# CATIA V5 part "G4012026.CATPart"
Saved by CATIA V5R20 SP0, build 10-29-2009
Part number: G4012026
Revision: 4
Definition: design
Nomenclature: G4012026
Source: made
Description: NOT SPECIFIED
Bounding box of the stored display mesh (mm): x 0 to 26, y -16 to 16, z -16 to 16
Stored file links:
  C:\Users\Raffaele\Desktop\3D X SITO CF\BOLEX\25-BUSH REF 401\G4012026.CATPart
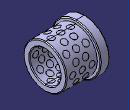
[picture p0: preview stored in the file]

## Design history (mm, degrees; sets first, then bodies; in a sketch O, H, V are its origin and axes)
Body1 "MANIFOLD_SOLID_BREP #5937" (main body)
  Solid1: solid without history
Body2 "MANIFOLD_SOLID_BREP #6084"
  Solid2: solid without history
Body3 "MANIFOLD_SOLID_BREP #6231"
  Solid3: solid without history
Body4 "MANIFOLD_SOLID_BREP #6378"
  Solid4: solid without history
Body5 "MANIFOLD_SOLID_BREP #6525"
  Solid5: solid without history
Body6 "MANIFOLD_SOLID_BREP #6674"
  Solid6: solid without history
Body7 "MANIFOLD_SOLID_BREP #6823"
  Solid7: solid without history
Body8 "MANIFOLD_SOLID_BREP #6972"
  Solid8: solid without history
Body9 "MANIFOLD_SOLID_BREP #7121"
  Solid9: solid without history
Body10 "MANIFOLD_SOLID_BREP #7270"
  Solid10: solid without history
Body11 "MANIFOLD_SOLID_BREP #7419"
  Solid11: solid without history
Body12 "MANIFOLD_SOLID_BREP #7568"
  Solid12: solid without history
Body13 "MANIFOLD_SOLID_BREP #7717"
  Solid13: solid without history
Body14 "MANIFOLD_SOLID_BREP #7866"
  Solid14: solid without history
Body15 "MANIFOLD_SOLID_BREP #8015"
  Solid15: solid without history
Body16 "MANIFOLD_SOLID_BREP #8164"
  Solid16: solid without history
Body17 "MANIFOLD_SOLID_BREP #8313"
  Solid17: solid without history
Body18 "MANIFOLD_SOLID_BREP #8462"
  Solid18: solid without history
Body19 "MANIFOLD_SOLID_BREP #8611"
  Solid19: solid without history
Body20 "MANIFOLD_SOLID_BREP #8760"
  Solid20: solid without history
Body21 "MANIFOLD_SOLID_BREP #8909"
  Solid21: solid without history
Body22 "MANIFOLD_SOLID_BREP #9058"
  Solid22: solid without history
Body23 "MANIFOLD_SOLID_BREP #9207"
  Solid23: solid without history
Body24 "MANIFOLD_SOLID_BREP #9356"
  Solid24: solid without history
Body25 "MANIFOLD_SOLID_BREP #9505"
  Solid25: solid without history
Body26 "MANIFOLD_SOLID_BREP #9654"
  Solid26: solid without history
Body27 "MANIFOLD_SOLID_BREP #9803"
  Solid27: solid without history
Body28 "MANIFOLD_SOLID_BREP #9952"
  Solid28: solid without history
Body29 "MANIFOLD_SOLID_BREP #10101"
  Solid29: solid without history
Body30 "MANIFOLD_SOLID_BREP #10250"
  Solid30: solid without history
Body31 "MANIFOLD_SOLID_BREP #10399"
  Solid31: solid without history
Body32 "MANIFOLD_SOLID_BREP #10548"
  Solid32: solid without history
Body33 "MANIFOLD_SOLID_BREP #10695"
  Solid33: solid without history
Body34 "MANIFOLD_SOLID_BREP #10842"
  Solid34: solid without history
Body35 "MANIFOLD_SOLID_BREP #10991"
  Solid35: solid without history
Body36 "MANIFOLD_SOLID_BREP #11140"
  Solid36: solid without history
Body37 "MANIFOLD_SOLID_BREP #11289"
  Solid37: solid without history
Body38 "MANIFOLD_SOLID_BREP #11438"
  Solid38: solid without history
Body39 "MANIFOLD_SOLID_BREP #11587"
  Solid39: solid without history
Body40 "MANIFOLD_SOLID_BREP #11736"
  Solid40: solid without history
Body41 "MANIFOLD_SOLID_BREP #11885"
  Solid41: solid without history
